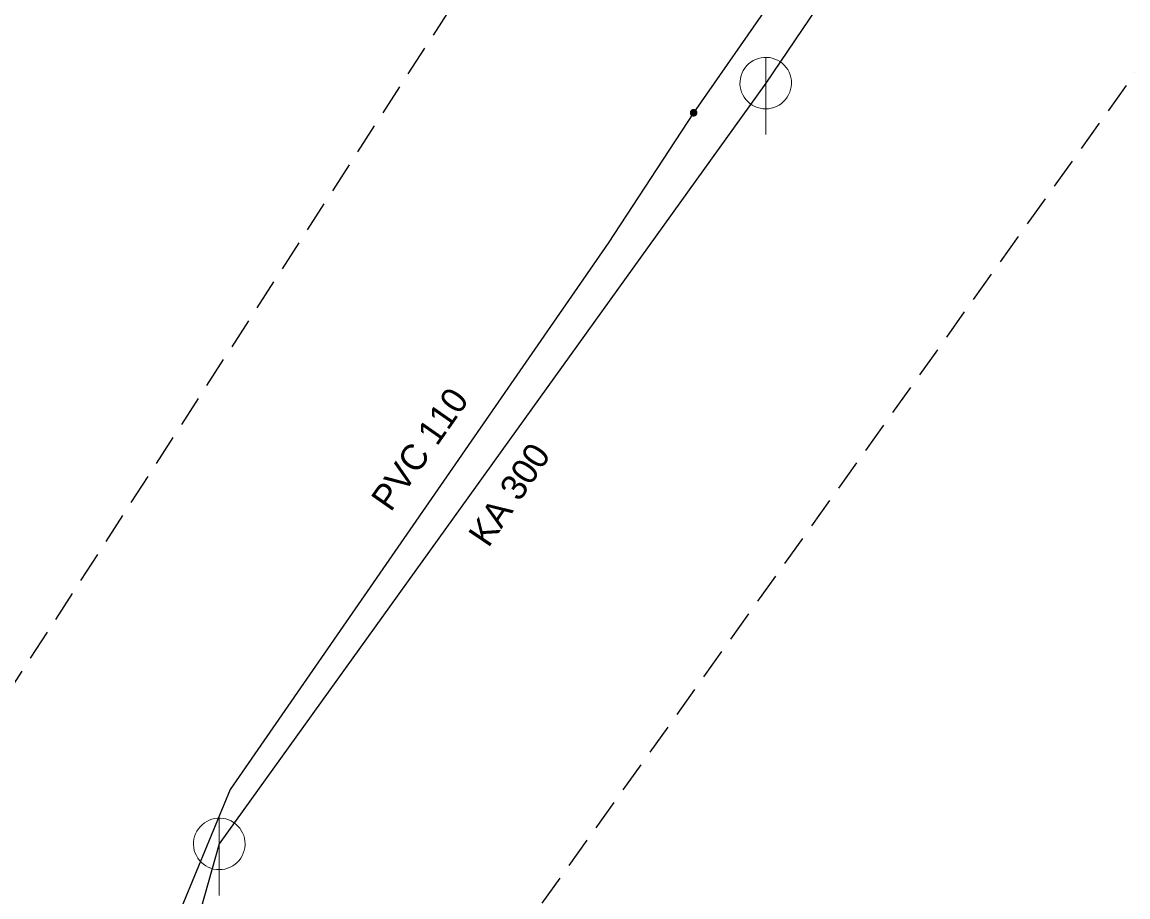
# Model space of a CAD drawing. Extents: x -686636 to -686482, y -972667 to -972167.
# Drawn here: x -686561.54 to -686518.64, y -972268.52 to -972234.56 of the extents above; entities that cross this region are included whole.
import ezdxf

# ---------------------------------------------------------------- set-up
doc = ezdxf.new("R2010")
doc.units = 0
doc.header["$LTSCALE"] = 0.4
doc.linetypes.add('MEDIUM_DASHED', pattern=[4.5, 3, -1.5])
for name, color, linetype, lineweight in [('1', 7, 'MEDIUM_DASHED', 25), ('14', 7, 'Continuous', 25), ('17', 7, 'Continuous', 25), ('22', 7, 'Continuous', 13), ('9', 7, 'Continuous', 13)]:
    doc.layers.add(name, color=color, linetype=linetype, lineweight=lineweight)

msp = doc.modelspace()

# ---------------------------------------------------------------- linework, layer by layer
at = {"layer": '1'}
msp.add_lwpolyline([(-686523.086, -972200.227), (-686492.539, -972167.269), (-686482.089, -972185.758), (-686542.379, -972270.164), (-686548.006, -972279.81), (-686543.183, -972295.084), (-686523.086, -972321.612), (-686521.478, -972360.197), (-686540.771, -972442.192), (-686521.478, -972473.543), (-686515.047, -972510.521), (-686519.067, -972578.85), (-686529.517, -972667.276), (-686549.614, -972665.668), (-686542.379, -972574.831), (-686589.003, -972562.773), (-686636.432, -972544.284), (-686625.981, -972525.795), (-686541.575, -972549.911), (-686539.967, -972501.678), (-686569.711, -972440.584), (-686549.614, -972329.65), (-686564.887, -972297.496), (-686572.926, -972277.399)], close=True, dxfattribs=at)
at = {"layer": '14'}
for p, q in [((-686519.433, -972217.405), (-686532.689, -972236.926)), ((-686532.689, -972236.926), (-686553.889, -972266.458)), ((-686553.889, -972266.458), (-686558.996, -972284.556))]:
    msp.add_line(p, q, dxfattribs=at)
at = {"layer": '17'}
msp.add_line((-686491.693, -972175.023), (-686535.487, -972238.079), dxfattribs=at)
msp.add_lwpolyline([(-686535.487, -972238.079), (-686538.799, -972243.136), (-686553.466, -972264.343), (-686555.427, -972269.103), (-686557.595, -972275.211), (-686559.928, -972284.685), (-686556.579, -972299.256)], dxfattribs=at)
at = {"layer": '22'}
for p, q in [((-686532.689, -972238.926), (-686532.688, -972235.926)), ((-686553.889, -972268.458), (-686553.888, -972265.458))]:
    msp.add_line(p, q, dxfattribs=at)
for points in [[(-686531.689, -972236.926), (-686531.694, -972236.817), (-686531.712, -972236.709), (-686531.742, -972236.603), (-686531.782, -972236.502), (-686531.834, -972236.405), (-686531.896, -972236.315), (-686531.968, -972236.232), (-686532.048, -972236.158), (-686532.136, -972236.092), (-686532.23, -972236.037), (-686532.33, -972235.992), (-686532.435, -972235.959), (-686532.542, -972235.937), (-686532.651, -972235.927), (-686532.761, -972235.929), (-686532.869, -972235.943), (-686532.976, -972235.968), (-686533.079, -972236.005), (-686533.177, -972236.054), (-686533.269, -972236.112), (-686533.355, -972236.181), (-686533.432, -972236.258), (-686533.501, -972236.344), (-686533.56, -972236.436), (-686533.608, -972236.534), (-686533.645, -972236.637), (-686533.671, -972236.744), (-686533.685, -972236.852), (-686533.688, -972236.962), (-686533.678, -972237.071), (-686533.657, -972237.178), (-686533.623, -972237.282), (-686533.579, -972237.382), (-686533.524, -972237.477), (-686533.458, -972237.565), (-686533.384, -972237.645), (-686533.301, -972237.717), (-686533.211, -972237.779), (-686533.115, -972237.831), (-686533.013, -972237.872), (-686532.908, -972237.902), (-686532.8, -972237.92), (-686532.69, -972237.926), (-686532.581, -972237.92), (-686532.473, -972237.902), (-686532.368, -972237.873), (-686532.266, -972237.832), (-686532.169, -972237.78), (-686532.079, -972237.718), (-686531.996, -972237.647), (-686531.921, -972237.567), (-686531.856, -972237.479), (-686531.8, -972237.385), (-686531.756, -972237.285), (-686531.722, -972237.181), (-686531.7, -972237.073), (-686531.69, -972236.964)], [(-686552.889, -972266.458), (-686552.894, -972266.349), (-686552.912, -972266.241), (-686552.942, -972266.135), (-686552.982, -972266.034), (-686553.034, -972265.937), (-686553.096, -972265.847), (-686553.168, -972265.764), (-686553.248, -972265.69), (-686553.336, -972265.624), (-686553.43, -972265.569), (-686553.53, -972265.524), (-686553.635, -972265.491), (-686553.742, -972265.469), (-686553.851, -972265.459), (-686553.961, -972265.461), (-686554.069, -972265.475), (-686554.176, -972265.5), (-686554.279, -972265.537), (-686554.377, -972265.586), (-686554.469, -972265.644), (-686554.555, -972265.713), (-686554.632, -972265.79), (-686554.701, -972265.876), (-686554.76, -972265.968), (-686554.808, -972266.066), (-686554.845, -972266.169), (-686554.871, -972266.276), (-686554.885, -972266.384), (-686554.888, -972266.494), (-686554.878, -972266.603), (-686554.857, -972266.71), (-686554.823, -972266.814), (-686554.779, -972266.914), (-686554.724, -972267.009), (-686554.658, -972267.097), (-686554.584, -972267.177), (-686554.501, -972267.249), (-686554.411, -972267.311), (-686554.315, -972267.363), (-686554.213, -972267.404), (-686554.108, -972267.434), (-686554, -972267.452), (-686553.89, -972267.458), (-686553.781, -972267.452), (-686553.673, -972267.434), (-686553.568, -972267.405), (-686553.466, -972267.364), (-686553.369, -972267.312), (-686553.279, -972267.25), (-686553.196, -972267.179), (-686553.121, -972267.099), (-686553.056, -972267.011), (-686553, -972266.917), (-686552.956, -972266.817), (-686552.922, -972266.713), (-686552.9, -972266.605), (-686552.89, -972266.496)]]:
    msp.add_lwpolyline(points, close=True, dxfattribs=at)
at = {"layer": '9'}
for points in [[(-686535.613, -972238.079), (-686535.613, -972238.092), (-686535.61, -972238.105), (-686535.608, -972238.118), (-686535.603, -972238.13), (-686535.597, -972238.142), (-686535.59, -972238.153), (-686535.581, -972238.163), (-686535.571, -972238.173), (-686535.561, -972238.181), (-686535.551, -972238.188), (-686535.539, -972238.194), (-686535.527, -972238.199), (-686535.514, -972238.202), (-686535.5, -972238.204), (-686535.488, -972238.206), (-686535.475, -972238.205), (-686535.462, -972238.203), (-686535.449, -972238.2), (-686535.436, -972238.195), (-686535.424, -972238.189), (-686535.414, -972238.182), (-686535.404, -972238.174), (-686535.394, -972238.164), (-686535.386, -972238.154), (-686535.379, -972238.143), (-686535.373, -972238.131), (-686535.368, -972238.119), (-686535.365, -972238.106), (-686535.363, -972238.093), (-686535.36, -972238.08), (-686535.362, -972238.067), (-686535.364, -972238.054), (-686535.367, -972238.041), (-686535.372, -972238.029), (-686535.377, -972238.017), (-686535.385, -972238.006), (-686535.392, -972237.996), (-686535.402, -972237.986), (-686535.413, -972237.978), (-686535.424, -972237.971), (-686535.436, -972237.965), (-686535.448, -972237.96), (-686535.461, -972237.957), (-686535.473, -972237.955), (-686535.487, -972237.954), (-686535.5, -972237.954), (-686535.512, -972237.956), (-686535.526, -972237.959), (-686535.538, -972237.964), (-686535.549, -972237.97), (-686535.561, -972237.977), (-686535.571, -972237.985), (-686535.581, -972237.995), (-686535.588, -972238.005), (-686535.596, -972238.016), (-686535.602, -972238.028), (-686535.607, -972238.04), (-686535.61, -972238.053), (-686535.612, -972238.066)], [(-686535.593, -972238.079), (-686535.593, -972238.09), (-686535.592, -972238.101), (-686535.588, -972238.112), (-686535.585, -972238.122), (-686535.58, -972238.132), (-686535.574, -972238.141), (-686535.566, -972238.15), (-686535.559, -972238.158), (-686535.549, -972238.165), (-686535.541, -972238.171), (-686535.531, -972238.176), (-686535.521, -972238.18), (-686535.51, -972238.183), (-686535.499, -972238.186), (-686535.488, -972238.186), (-686535.477, -972238.186), (-686535.466, -972238.184), (-686535.455, -972238.181), (-686535.445, -972238.177), (-686535.434, -972238.172), (-686535.426, -972238.166), (-686535.417, -972238.159), (-686535.409, -972238.151), (-686535.402, -972238.142), (-686535.396, -972238.133), (-686535.391, -972238.123), (-686535.387, -972238.113), (-686535.384, -972238.102), (-686535.382, -972238.091), (-686535.38, -972238.08), (-686535.38, -972238.069), (-686535.382, -972238.058), (-686535.386, -972238.047), (-686535.39, -972238.037), (-686535.395, -972238.027), (-686535.401, -972238.018), (-686535.407, -972238.009), (-686535.416, -972238.001), (-686535.424, -972237.994), (-686535.434, -972237.988), (-686535.444, -972237.983), (-686535.453, -972237.979), (-686535.465, -972237.976), (-686535.475, -972237.974), (-686535.487, -972237.974), (-686535.498, -972237.973), (-686535.509, -972237.975), (-686535.52, -972237.978), (-686535.529, -972237.982), (-686535.539, -972237.987), (-686535.549, -972237.993), (-686535.558, -972238), (-686535.566, -972238.008), (-686535.573, -972238.017), (-686535.578, -972238.026), (-686535.583, -972238.036), (-686535.588, -972238.046), (-686535.591, -972238.057), (-686535.593, -972238.068)], [(-686535.574, -972238.079), (-686535.574, -972238.088), (-686535.573, -972238.097), (-686535.57, -972238.106), (-686535.566, -972238.114), (-686535.563, -972238.122), (-686535.558, -972238.13), (-686535.551, -972238.137), (-686535.546, -972238.143), (-686535.539, -972238.149), (-686535.531, -972238.154), (-686535.522, -972238.158), (-686535.515, -972238.161), (-686535.505, -972238.164), (-686535.497, -972238.165), (-686535.488, -972238.167), (-686535.478, -972238.166), (-686535.47, -972238.165), (-686535.461, -972238.162), (-686535.453, -972238.159), (-686535.445, -972238.155), (-686535.436, -972238.15), (-686535.429, -972238.144), (-686535.424, -972238.138), (-686535.418, -972238.131), (-686535.413, -972238.123), (-686535.409, -972238.115), (-686535.406, -972238.107), (-686535.402, -972238.098), (-686535.402, -972238.089), (-686535.399, -972238.08), (-686535.401, -972238.071), (-686535.402, -972238.062), (-686535.404, -972238.053), (-686535.407, -972238.045), (-686535.412, -972238.037), (-686535.417, -972238.029), (-686535.423, -972238.022), (-686535.429, -972238.016), (-686535.436, -972238.01), (-686535.444, -972238.005), (-686535.451, -972238.001), (-686535.46, -972237.998), (-686535.468, -972237.995), (-686535.478, -972237.994), (-686535.487, -972237.993), (-686535.495, -972237.993), (-686535.505, -972237.994), (-686535.514, -972237.997), (-686535.522, -972238), (-686535.529, -972238.004), (-686535.538, -972238.009), (-686535.544, -972238.015), (-686535.551, -972238.021), (-686535.556, -972238.028), (-686535.561, -972238.036), (-686535.566, -972238.044), (-686535.569, -972238.052), (-686535.571, -972238.061), (-686535.573, -972238.07)], [(-686535.554, -972238.079), (-686535.554, -972238.086), (-686535.553, -972238.093), (-686535.551, -972238.1), (-686535.549, -972238.106), (-686535.546, -972238.112), (-686535.542, -972238.118), (-686535.538, -972238.124), (-686535.532, -972238.129), (-686535.527, -972238.133), (-686535.521, -972238.137), (-686535.515, -972238.14), (-686535.509, -972238.143), (-686535.502, -972238.144), (-686535.495, -972238.147), (-686535.488, -972238.147), (-686535.48, -972238.147), (-686535.473, -972238.145), (-686535.467, -972238.144), (-686535.461, -972238.141), (-686535.453, -972238.138), (-686535.449, -972238.134), (-686535.443, -972238.13), (-686535.438, -972238.125), (-686535.434, -972238.119), (-686535.429, -972238.113), (-686535.426, -972238.107), (-686535.424, -972238.101), (-686535.422, -972238.094), (-686535.421, -972238.087), (-686535.419, -972238.08), (-686535.419, -972238.073), (-686535.421, -972238.066), (-686535.423, -972238.059), (-686535.426, -972238.053), (-686535.429, -972238.046), (-686535.433, -972238.041), (-686535.436, -972238.035), (-686535.441, -972238.03), (-686535.448, -972238.026), (-686535.453, -972238.022), (-686535.46, -972238.019), (-686535.466, -972238.016), (-686535.473, -972238.014), (-686535.48, -972238.013), (-686535.487, -972238.013), (-686535.494, -972238.013), (-686535.5, -972238.013), (-686535.507, -972238.015), (-686535.514, -972238.018), (-686535.52, -972238.021), (-686535.526, -972238.025), (-686535.532, -972238.029), (-686535.537, -972238.034), (-686535.541, -972238.04), (-686535.544, -972238.045), (-686535.548, -972238.052), (-686535.551, -972238.058), (-686535.551, -972238.065), (-686535.554, -972238.072)], [(-686535.534, -972238.079), (-686535.534, -972238.084), (-686535.534, -972238.089), (-686535.532, -972238.094), (-686535.531, -972238.098), (-686535.529, -972238.103), (-686535.526, -972238.107), (-686535.522, -972238.11), (-686535.519, -972238.114), (-686535.516, -972238.117), (-686535.512, -972238.12), (-686535.507, -972238.122), (-686535.502, -972238.124), (-686535.498, -972238.125), (-686535.493, -972238.127), (-686535.488, -972238.127), (-686535.483, -972238.127), (-686535.478, -972238.126), (-686535.473, -972238.125), (-686535.468, -972238.123), (-686535.463, -972238.121), (-686535.46, -972238.118), (-686535.456, -972238.115), (-686535.453, -972238.111), (-686535.45, -972238.108), (-686535.446, -972238.104), (-686535.445, -972238.099), (-686535.443, -972238.095), (-686535.441, -972238.09), (-686535.441, -972238.085), (-686535.44, -972238.08), (-686535.44, -972238.075), (-686535.441, -972238.07), (-686535.441, -972238.065), (-686535.444, -972238.061), (-686535.446, -972238.056), (-686535.449, -972238.052), (-686535.451, -972238.048), (-686535.455, -972238.045), (-686535.458, -972238.042), (-686535.463, -972238.039), (-686535.468, -972238.037), (-686535.472, -972238.035), (-686535.477, -972238.034), (-686535.482, -972238.033), (-686535.487, -972238.033), (-686535.492, -972238.033), (-686535.497, -972238.034), (-686535.502, -972238.034), (-686535.505, -972238.036), (-686535.511, -972238.038), (-686535.515, -972238.041), (-686535.517, -972238.044), (-686535.522, -972238.047), (-686535.524, -972238.051), (-686535.527, -972238.055), (-686535.529, -972238.06), (-686535.532, -972238.064), (-686535.532, -972238.069), (-686535.534, -972238.074)], [(-686535.514, -972238.079), (-686535.514, -972238.082), (-686535.515, -972238.085), (-686535.514, -972238.087), (-686535.512, -972238.09), (-686535.512, -972238.093), (-686535.51, -972238.095), (-686535.507, -972238.097), (-686535.505, -972238.099), (-686535.504, -972238.101), (-686535.502, -972238.103), (-686535.499, -972238.105), (-686535.495, -972238.106), (-686535.494, -972238.106), (-686535.49, -972238.107), (-686535.488, -972238.107), (-686535.485, -972238.107), (-686535.482, -972238.107), (-686535.478, -972238.106), (-686535.477, -972238.105), (-686535.473, -972238.104), (-686535.472, -972238.102), (-686535.468, -972238.1), (-686535.467, -972238.098), (-686535.466, -972238.096), (-686535.463, -972238.094), (-686535.463, -972238.091), (-686535.461, -972238.088), (-686535.461, -972238.086), (-686535.46, -972238.083), (-686535.458, -972238.08), (-686535.46, -972238.077), (-686535.46, -972238.074), (-686535.461, -972238.071), (-686535.462, -972238.069), (-686535.463, -972238.066), (-686535.465, -972238.064), (-686535.466, -972238.061), (-686535.468, -972238.059), (-686535.471, -972238.058), (-686535.473, -972238.056), (-686535.475, -972238.055), (-686535.478, -972238.054), (-686535.48, -972238.053), (-686535.483, -972238.053), (-686535.487, -972238.052), (-686535.49, -972238.053), (-686535.493, -972238.052), (-686535.495, -972238.054), (-686535.498, -972238.054), (-686535.5, -972238.055), (-686535.502, -972238.057), (-686535.505, -972238.058), (-686535.507, -972238.06), (-686535.509, -972238.063), (-686535.511, -972238.065), (-686535.512, -972238.068), (-686535.512, -972238.07), (-686535.514, -972238.073), (-686535.514, -972238.076)], [(-686535.495, -972238.079), (-686535.495, -972238.081), (-686535.495, -972238.081), (-686535.494, -972238.081), (-686535.494, -972238.083), (-686535.495, -972238.084), (-686535.493, -972238.084), (-686535.493, -972238.084), (-686535.493, -972238.086), (-686535.493, -972238.086), (-686535.492, -972238.087), (-686535.49, -972238.087), (-686535.49, -972238.087), (-686535.49, -972238.088), (-686535.488, -972238.088), (-686535.488, -972238.088), (-686535.487, -972238.088), (-686535.485, -972238.088), (-686535.485, -972238.087), (-686535.485, -972238.087), (-686535.483, -972238.087), (-686535.483, -972238.086), (-686535.483, -972238.086), (-686535.482, -972238.085), (-686535.482, -972238.085), (-686535.48, -972238.084), (-686535.48, -972238.083), (-686535.478, -972238.082), (-686535.478, -972238.082), (-686535.478, -972238.081), (-686535.478, -972238.08), (-686535.478, -972238.079), (-686535.478, -972238.078), (-686535.478, -972238.078), (-686535.48, -972238.077), (-686535.48, -972238.076), (-686535.48, -972238.075), (-686535.48, -972238.075), (-686535.482, -972238.074), (-686535.482, -972238.074), (-686535.483, -972238.073), (-686535.483, -972238.073), (-686535.485, -972238.072), (-686535.485, -972238.072), (-686535.485, -972238.072), (-686535.487, -972238.072), (-686535.488, -972238.072), (-686535.489, -972238.072), (-686535.489, -972238.072), (-686535.49, -972238.073), (-686535.49, -972238.072), (-686535.492, -972238.074), (-686535.492, -972238.074), (-686535.493, -972238.074), (-686535.493, -972238.074), (-686535.494, -972238.076), (-686535.494, -972238.077), (-686535.494, -972238.078), (-686535.495, -972238.078), (-686535.495, -972238.079)]]:
    msp.add_lwpolyline(points, close=True, dxfattribs=at)

# ---------------------------------------------------------------- texts
at = {"layer": '1'}
for s, rotation, p in [('PVC 110 ', 55, (-686547.238, -972253.607)), ('KA 300', 56, (-686543.45, -972254.993))]:
    msp.add_text(s, height=1, rotation=rotation, dxfattribs=at).set_placement(p)

doc.saveas('drawing.dxf')
